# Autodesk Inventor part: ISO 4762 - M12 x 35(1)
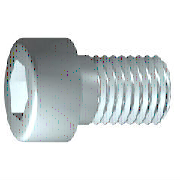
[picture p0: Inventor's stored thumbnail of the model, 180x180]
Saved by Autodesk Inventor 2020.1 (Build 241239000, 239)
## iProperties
Created: 2019-01
Part Number: ISO 4762 - M12 x 35(1)
Material: Edelstahl, 440C
Description: Innensechskantschraube
Document SubType Name: Modeling
Standard: ISO 4762
Designer: lutzd
Standard Revision: Fourth edition 2004-03-01
Standards Organization: ISO
Language: de-DE
Size Designation: M12 x 35
Categories: <MemberInstance><Categories><Category DisplayName="Verbindungselemente" InternalName="e4da775c-781d-43d5-af7c-5136215cf5a6" Mnemonic="FSTN"><Category DisplayNam
Mass: 49.1501 g
Surface Area: 26.8181 cm^2
Volume: 6.34195 cm^3
Density: 7.75 g/cm^3
Appearance: Semi-Polished(3)
IsCustomPart: 0
Author: lutzd
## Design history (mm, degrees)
body "Solid1"
sketch "Skizze1"
  geometry: L1 (-2.667, 0)-(35, 0); L2 (35, 0)-(35, 6); L3 (35, 6)-(4.375, 6); L4 (4.375, 6)-(3.301, 6); L5 (3.301, 6)-(0, 6); L6 (0, 6)-(0, 9); L7 (0, 9)-(-12, 9); L8 (-12, 9)-(-12, 5.774); L9 (-12, 5.774)-(-6, 5.774); L10 (-6, 5.774)-(-2.667, 0); L11 (-21.4, 0)-(44.4, 0) reference; L12 (0, -1.8)-(0, 10.8) reference; L13 (4.375, 6)-(0, 6)
  constraints: 22 end point, 6 parallel, 2 collinear, 2 perpendicular, 1 horizontal, 1 point on line
  dimensions: "d1" = 30.625 distance from line of L3.end L2 (= GEL); "d2" = 1.07364 distance of L4.end L3.end (computed from GAL); "d3" = 12 distance between parallel lines of L8 L6 (= KOH); "d4" = 6 distance of L8.end L9.end (= INTI); "d5" = 60 deg angle of L10 L1; "d6" = 12 diameter of L3 L1 (= GD); "d7" = 12 diameter of L5 L1 (= BDM); "d8" = 11.54701 diameter of L9 L1 (= 1.1547 x SW); "d9" = 18 diameter of L7 L1 (= KOD); "d26" = 35 distance between parallel lines of L12 L2 (= NLG)
workplane "Work Plane1"
fillet "Fillet2" dims "d30" = 0.1 (= R)
revolve "Körper" stored, may be unused: angle "d10" = 90 deg
sketch "Skizze2"
  geometry: L1 (0, -12.6)-(0, 12.6) reference; L2 (-12.6, 0)-(12.6, 0) reference; L3 (5.774, 0)-(2.887, -5); L4 (2.887, -5)-(-2.887, -5); L5 (-2.887, -5)-(-5.774, 0); L6 (-5.774, 0)-(-2.887, 5); L7 (-2.887, 5)-(2.887, 5); L8 (2.887, 5)-(5.774, 0); 2 further points
  constraints: 12 end point, 1 coincident, 1 horizontal alignment, 1 point on line, 12 other
extrude "Loch" join sketch "Skizze2" stored distance "d11" = 10; taper "d12" = 0 deg
fillet "Rundung1" dims "d17" = 1.2 (= RR)
feature "Gewinde" dims "d13" = 30.625 (= GEL), "d14" = 0
chamfer "Fase1" distance "d15" = 1.07354 (= -0.5 x SPD + 0.5 x GD); stored, may be unused: second distance "d16" = 1.07354 (= GUL), angle "d27" = 45 deg
other parameters: "GD" = 12 [user parameter; used in 2 equation terms], "NLG" = 35 [user parameter; used in 1 equation term], "GEL" = 30.625 [user parameter; used in 2 equation terms], "KOD" = 18 [user parameter; used in 1 equation term], "KOH" = 12 [user parameter; used in 1 equation term], "INTI" = 6 [user parameter; used in 1 equation term], "GAL" = 1.07354 (= 0.61345 x PTC) [user parameter; used in 1 equation term], "GUL" = 1.07354 (= 0.61345 x PTC) [user parameter; used in 1 equation term], "BDM" = 12 (= NND) [user parameter; used in 1 equation term], "RR" = 1.2 [user parameter; used in 1 equation term], "SPD" = 9.85293 (= NND - 1.2269 x PTC) [user parameter; used in 1 equation term], "d19" = 0, "d28" = 0, "d29" = 0, "R" = 0.1 [user parameter; used in 1 equation term], "TOA" = 30 deg [user parameter], "GD1" = 9.85293 (= THREADDIA - 1.2269 x PTC) [user parameter], "THREADDIA" = 12 [user parameter; used in 1 equation term], "FAWI" = 45 deg [user parameter], "TPU" = 5.71429 (computed from PTC) [user parameter], "PTC" = 1.75 [user parameter; used in 5 equation terms], "NND" = 12 [user parameter; used in 2 equation terms], "E0" = 11.55 (= 1.155 x SW) [user parameter]
